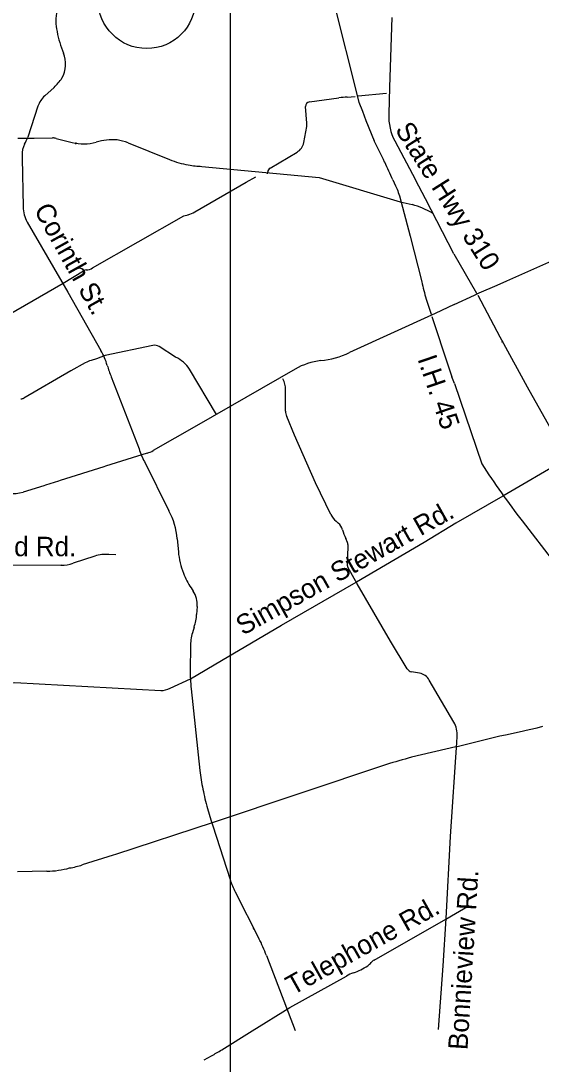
# Model space of a CAD drawing. Extents: x 105094 to 105814, y -291615 to -291123.
# Drawn here: x 105446.1 to 105478.5, y -291559.2 to -291494.1 of the extents above; entities that cross this region are included whole.
import ezdxf

# ---------------------------------------------------------------- set-up
doc = ezdxf.new("R2010")
doc.units = 0
doc.layers.add('G_BORDER', color=7, linetype='Continuous')
doc.layers.add('G_MAP', color=7, linetype='Continuous')

msp = doc.modelspace()

# ---------------------------------------------------------------- linework, layer by layer
at = {"layer": 'G_BORDER'}
msp.add_line((105459.139, -291158.398), (105459.139, -291578.398), dxfattribs=at)
msp.add_circle((105453.937, -291492.836), 3.035, dxfattribs=at)
at = {"layer": 'G_MAP'}
for p, q in [((105462.788, -291481.871), (105467.151, -291499.204)), ((105469.222, -291493.927), (105469.073, -291498.28)), ((105448.157, -291498.29), (105447.577, -291498.821)), ((105469.073, -291498.28), (105469.016, -291499.969)), ((105464.07, -291499.193), (105465.918, -291498.952)), ((105466.428, -291498.894), (105466.929, -291498.852)), ((105467.116, -291498.826), (105468.879, -291498.655)), ((105447.149, -291499.469), (105446.531, -291501.393)), ((105463.918, -291500.517), (105463.837, -291499.48)), ((105463.721, -291501.732), (105463.908, -291500.725)), ((105446.308, -291501.839), (105446.243, -291502.004)), ((105448.293, -291501.474), (105449.284, -291501.729)), ((105449.508, -291501.733), (105449.502, -291501.829)), ((105452.772, -291501.753), (105455.352, -291502.797)), ((105469.4, -291501.631), (105470.688, -291504.061)), ((105461.621, -291503.328), (105463.301, -291502.333)), ((105446.172, -291502.701), (105446.222, -291505.743)), ((105457.372, -291503.221), (105464.687, -291503.919)), ((105461.461, -291503.677), (105461.473, -291503.561)), ((105464.687, -291503.919), (105469.722, -291505.437)), ((105469.283, -291504.068), (105469.445, -291504.426)), ((105469.445, -291504.426), (105469.541, -291504.642)), ((105469.7, -291505.053), (105470.365, -291507.572)), ((105469.722, -291505.437), (105470.485, -291505.606)), ((105470.365, -291507.572), (105471.076, -291510.417)), ((105473.084, -291508.673), (105474.489, -291511.127)), ((105476.385, -291510.349), (105479.178, -291509.112)), ((105474.654, -291511.108), (105475.784, -291510.627)), ((105475.784, -291510.627), (105476.385, -291510.349)), ((105471.357, -291511.495), (105471.657, -291512.448)), ((105473.107, -291511.825), (105474.37, -291511.25)), ((105474.37, -291511.25), (105474.654, -291511.108)), ((105474.573, -291511.247), (105475.952, -291513.859)), ((105473.107, -291511.825), (105471.906, -291512.4)), ((105471.906, -291512.4), (105466.571, -291514.836)), ((105471.699, -291512.58), (105472.745, -291515.719)), ((105475.952, -291513.859), (105476.059, -291514.037)), ((105476.059, -291514.037), (105477.644, -291516.979)), ((105476.059, -291514.169), (105476.152, -291514.134)), ((105455.735, -291515.119), (105454.706, -291514.459)), ((105472.745, -291515.719), (105472.946, -291516.352)), ((105451.72, -291516.348), (105453.455, -291520.831)), ((105473.12, -291516.772), (105472.946, -291516.352)), ((105473.12, -291516.772), (105474.815, -291521.765)), ((105462.582, -291518.491), (105462.585, -291517.154)), ((105477.644, -291516.979), (105481.513, -291523.864)), ((105451.265, -291521.952), (105448.54, -291522.824)), ((105451.369, -291521.92), (105451.265, -291521.952)), ((105453.797, -291521.639), (105455.312, -291524.703)), ((105479.979, -291521.549), (105476.14, -291523.793)), ((105447.516, -291523.15), (105446.224, -291523.535)), ((105447.626, -291523.105), (105447.516, -291523.15)), ((105448.439, -291522.85), (105447.626, -291523.105)), ((105448.54, -291522.824), (105448.439, -291522.85)), ((105476.14, -291523.793), (105473.211, -291525.482)), ((105465.876, -291525.475), (105465.737, -291525.353)), ((105477.347, -291525.34), (105479.363, -291527.943)), ((105455.836, -291526.454), (105455.904, -291527.263)), ((105466.446, -291526.678), (105466.344, -291526.422)), ((105466.452, -291528.146), (105466.488, -291526.916)), ((105450.705, -291527.531), (105449.357, -291527.975)), ((105452.002, -291527.461), (105451.563, -291527.427)), ((105448.589, -291528.101), (105444.347, -291528.12)), ((105467.058, -291529.26), (105466.475, -291528.228)), ((105456.7, -291529.517), (105456.828, -291529.711)), ((105457.079, -291530.666), (105457.043, -291531.166)), ((105456.885, -291531.954), (105456.783, -291532.315)), ((105456.659, -291533.184), (105456.645, -291534.611)), ((105470.939, -291534.836), (105470.446, -291534.748)), ((105455.384, -291535.765), (105456.672, -291535.186)), ((105473.076, -291537.886), (105471.546, -291535.261)), ((105456.703, -291535.806), (105457.245, -291540.909)), ((105477.771, -291538.351), (105478.265, -291538.235)), ((105478.265, -291538.235), (105478.617, -291538.148)), ((105473.207, -291539.436), (105475.949, -291538.748)), ((105473.266, -291539.159), (105473.289, -291538.791)), ((105475.949, -291538.748), (105476.298, -291538.671)), ((105476.298, -291538.671), (105477.151, -291538.484)), ((105477.151, -291538.484), (105477.771, -291538.351)), ((105473.207, -291539.436), (105470.433, -291540.082)), ((105468.883, -291540.531), (105458.08, -291544.158)), ((105457.72, -291543.271), (105457.932, -291543.98)), ((105458.08, -291544.158), (105451.983, -291546.137)), ((105457.932, -291543.98), (105458.061, -291544.358)), ((105458.061, -291544.358), (105459.127, -291547.713)), ((105451.837, -291546.182), (105449.918, -291546.79)), ((105451.983, -291546.137), (105451.837, -291546.182)), ((105447.708, -291547.19), (105445.869, -291547.232)), ((105459.456, -291548.479), (105460.929, -291551.383)), ((105460.564, -291550.784), (105460.661, -291550.733)), ((105461.4, -291552.445), (105463.193, -291557.124)), ((105458.61, -291558.327), (105460.506, -291557.153))]:
    msp.add_line(p, q, dxfattribs=at)
for points in [[(105467.151, -291499.204), (105467.374, -291499.785), (105467.591, -291500.351), (105468.117, -291501.616)], [(105445.901, -291501.464), (105446.925, -291501.452), (105448.049, -291501.444)], [(105456.923, -291506.064), (105460.134, -291504.21), (105460.741, -291503.871)], [(105473.084, -291508.673), (105471.305, -291505.246), (105470.688, -291504.061)], [(105450.561, -291509.558), (105456.245, -291506.299), (105456.506, -291506.233)], [(105446.484, -291506.69), (105449.008, -291511.056), (105451.079, -291514.706)], [(105443.89, -291513.291), (105448.72, -291510.51), (105449.989, -291509.735)], [(105454.317, -291514.387), (105451.34, -291515.012), (105450.807, -291515.228), (105450.462, -291515.326)], [(105450.104, -291515.475), (105449.198, -291515.978), (105446.275, -291517.67)], [(105463.189, -291515.864), (105457.046, -291519.407), (105454.327, -291520.941)], [(105458.274, -291518.699), (105456.603, -291515.868)], [(105465.415, -291524.932), (105464.458, -291522.969), (105463.147, -291519.995), (105462.657, -291518.822)], [(105453.956, -291521.103), (105453.029, -291521.4), (105451.369, -291521.92)], [(105473.211, -291525.482), (105471.237, -291526.677), (105467.01, -291529.157)], [(105456.672, -291535.186), (105458.603, -291534.046), (105462.327, -291531.837), (105466.984, -291529.151)], [(105470.174, -291534.562), (105469.122, -291532.839), (105467.058, -291529.26)], [(105437.246, -291535.477), (105437.992, -291535.477), (105445.701, -291535.409), (105454.809, -291535.915)], [(105472.129, -291557.059), (105472.42, -291553.097), (105472.591, -291550.142), (105472.878, -291545.013), (105473.266, -291539.159)], [(105468.106, -291552.729), (105472.581, -291550.171), (105474.031, -291549.325)], [(105460.506, -291557.153), (105462.854, -291555.696), (105466.377, -291553.736)], [(105457.505, -291558.949), (105457.964, -291558.701)]]:
    msp.add_lwpolyline(points, dxfattribs=at)
for centre, radius, start, end in [((105451.357, -291494.118), 3.09, 168.37017, 192.97175), ((105455.307, -291493.468), 7.09, 190.92384, 202.21582), ((105447.074, -291496.831), 1.803, 330.64906, 22.22848), ((105446.087, -291496.033), 3.062, 312.5155, 326.67226), ((105448.658, -291500), 1.6, 132.51588, 160.58421), ((105464.105, -291499.46), 0.269, 97.40429, 184.33964), ((105466.752, -291504.012), 5.128, 93.62739, 99.36767), ((105463.138, -291500.58), 0.783, 349.35663, 4.62691), ((105472.324, -291500.081), 3.31, 178.06949, 207.92578), ((105440.17, -291498.492), 6.991, 331.39178, 335.47641), ((105448.056, -291502.394), 0.95, 75.55645, 90.39547), ((105450.004, -291498.947), 2.873, 255.48117, 285.84076), ((105451.878, -291505.54), 3.981, 87.06288, 105.88885), ((105451.621, -291504.603), 3.073, 68.01628, 81.37399), ((105462.849, -291501.57), 0.887, 300.64762, 349.47502), ((105404.232, -291533.242), 71.284, 25.13556, 26.33719), ((105447.661, -291502.501), 1.503, 160.69396, 187.67696), ((105457.438, -291497.637), 5.566, 247.99109, 260.57334), ((105457.586, -291497.417), 5.808, 259.48105, 267.88672), ((105433.698, -291520.056), 39.012, 24.19388, 25.98534), ((105461.777, -291503.591), 0.306, 120.64139, 174.27128), ((105473.5, -291503.351), 4.164, 198.07464, 204.12646), ((105448.174, -291505.713), 1.952, 180.86633, 210.01999), ((105469.198, -291510.385), 4.949, 59.04167, 74.92892), ((105456.104, -291504.647), 1.636, 284.20379, 300.01885), ((105450.084, -291508.721), 0.963, 274.29398, 299.67553), ((105450.187, -291510.063), 0.383, 94.5307, 121.05329), ((105489.808, -291506.112), 19.221, 192.94036, 196.26342), ((105447.297, -291516.852), 4.349, 16.25193, 29.57811), ((105454.424, -291514.898), 0.521, 57.32779, 101.8706), ((105464.096, -291509.466), 5.913, 276.69249, 294.73741), ((105450.925, -291516.952), 1.69, 105.88263, 119.05825), ((105454.92, -291516.896), 1.955, 48.33474, 65.35382), ((105455.29, -291516.643), 1.525, 30.55568, 52.4212), ((105465.25, -291519.436), 4.124, 96.46964, 119.98373), ((105462.184, -291512.301), 11.219, 197.28919, 201.14374), ((105461.345, -291517.113), 1.241, 358.10915, 30.78547), ((105446.086, -291517.343), 0.378, 270.25553, 300.10931), ((105463.61, -291518.43), 1.03, 183.37569, 202.36334), ((105456.433, -291520.045), 3.081, 194.79524, 211.16115), ((105453.772, -291520.173), 0.948, 281.16599, 305.8309), ((105514.578, -291496.288), 47.224, 212.64858, 217.96561), ((105445.592, -291521.415), 2.212, 241.57968, 286.59888), ((105451.41, -291526.825), 4.441, 4.79885, 28.53688), ((105466.619, -291524.345), 1.34, 205.98449, 228.81789), ((105465.334, -291526.094), 0.823, 14.66864, 48.82335), ((105468.533, -291525.238), 2.489, 195.10108, 208.40923), ((105465.902, -291526.895), 0.586, 357.93196, 21.69048), ((105451.391, -291529.61), 2.19, 85.50096, 108.26116), ((105460.549, -291526.875), 4.661, 184.77396, 201.6465), ((105448.577, -291525.612), 2.488, 270.26875, 288.26117), ((105466.626, -291528.143), 0.174, 180.80655, 209.33989), ((105460.943, -291526.705), 5.091, 201.79629, 213.52877), ((105455.552, -291530.556), 1.531, 355.87831, 33.52684), ((105454.402, -291531.045), 2.644, 339.90201, 357.38661), ((105459.943, -291533.209), 3.284, 164.19691, 179.55149), ((105467.073, -291534.705), 10.429, 179.48463, 186.0617), ((105470.517, -291534.353), 0.401, 211.37696, 259.819), ((105470.783, -291535.706), 0.883, 30.24621, 79.86912), ((105454.784, -291534.643), 1.273, 271.13353, 298.12566), ((105471.703, -291538.686), 1.59, 356.24033, 30.24684), ((105481.98, -291582.86), 44.308, 105.10518, 107.19222), ((105467.068, -291539.866), 9.878, 186.06002, 192.84398), ((105467.683, -291540.303), 10.395, 189.73825, 196.58706), ((105447.578, -291541.219), 5.972, 271.25313, 285.04219), ((105448.033, -291540.897), 6.187, 280.19536, 287.73841), ((105462.731, -291546.615), 3.768, 196.93848, 209.63622), ((105450.869, -291556.482), 11.278, 20.97424, 26.87893), ((105465.239, -291549.266), 4.548, 290.37494, 302.919), ((105466.323, -291551.316), 2.248, 308.12874, 315.65442), ((105468.387, -291553.219), 0.565, 119.81347, 143.94902), ((105467.287, -291555.114), 1.651, 106.3219, 123.43719), ((105451.965, -291547.595), 12.623, 298.37674, 301.76897)]:
    msp.add_arc(centre, radius, start, end, dxfattribs=at)

# ---------------------------------------------------------------- texts
for s, height, rotation, p in [('State Hwy 310', 1.21107, 302.30341, (105469.38, -291500.931)), ('Corinth St.', 1.21107, 299.15467, (105446.87, -291505.926)), ('I.H. 45', 1.2111, 288.85964, (105470.799, -291515.223)), ('Simpson Stewart Rd.', 1.21107, 29.2472, (105459.929, -291532.504)), ('Bonnieview Rd.', 1.21107, 86.49357, (105473.926, -291558.362)), ('Telephone Rd.', 1.21107, 29.2472, (105463.039, -291554.946))]:
    msp.add_text(s, height=height, rotation=rotation, dxfattribs=at).set_placement(p)
msp.add_text('Laureland Rd.', height=1.21107, dxfattribs=at).set_placement((105439.365, -291527.538))

doc.saveas('drawing.dxf')
